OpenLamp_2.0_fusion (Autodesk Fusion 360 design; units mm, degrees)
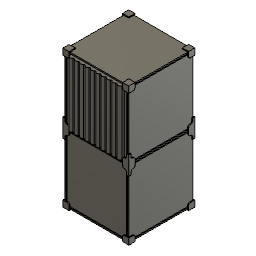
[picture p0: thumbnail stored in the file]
parameter "panel_l" = 100
parameter "proportion_const" = 8.3333 (= "panel_l / 12")
sketch "Sketch1" plane through (0, 0, 0) normal (0, 1, 0) x axis (1, 0, 0)
  line L1 (-50, 50) -> (50, 50)
  line L2 (-50, -50) -> (-50, 50)
  line L3 (50, -50) -> (-50, -50)
  line L4 (50, 50) -> (50, -50)
  line L5 (-50, -50) -> (50, 50)
  line L6 (50, -50) -> (-50, 50)
  point P6 (0, 0)
  point P1 (0, 0)
  point P4 (-50, -50)
  point P5 (50, -50)
  point P3 (-50, 50)
  horizontal L1
  perpendicular L1 L2
  parallel L1 L3
  parallel L2 L4
  coincident L5 P6
  coincident L6 P6
  coincident P1 P6
  dimension "d1" distance P4 P5 = 100 (= "panel_length")
  dimension "panel_length" distance P3 P4 = 100 (= "panel_l")
  dimension "panel_gap" distance = 1.5
  dimension "connector_thickness" distance = 1.5
  dimension "d55" distance = 9
  dimension "d122" distance = 8.3333 (= "proportion_const")
extrude "Extrude1" new body sketch "Sketch1" profile of L1 L2 L3 L4 along normal blind 2 named "panel_thickness"
work_plane "WorkPlane1" AlongDistance 1.5 (= "panel_gap")
sketch "Sketch3" plane through (0, 3.5, 0) normal (0, 1, 0) x axis (-1, 0, 0)
  line L1 (0, -142.7236) -> (0, 0)
  line L2 (48, -50) -> (50, -50)
  line L3 (48, 50) -> (48, -50)
  line L4 (50, 50) -> (48, 50)
  line L5 (50, -50) -> (50, 50)
  line L6 (50, 50) -> (50, -50)
  line L7 (-144.094, 0) -> (0, 0)
  line L8 (50, -50) -> (-50, -50)
  line L9 (-50, 50) -> (50, 50)
  line L10 (-50, -50) -> (-50, 50)
  line L11 (-48, 50) -> (-48, -50)
  line L12 (-50, 50) -> (-48, 50)
  line L13 (-48, -50) -> (-50, -50)
  line L14 (-46.5, 48) -> (46.5, 48)
  line L15 (-46.5, 50) -> (-46.5, 48)
  line L16 (46.5, 50) -> (-46.5, 50)
  line L17 (46.5, 48) -> (46.5, 50)
  line L18 (46.5, -50) -> (-46.5, -50)
  line L19 (-46.5, -48) -> (46.5, -48)
  line L20 (46.5, -48) -> (46.5, -50)
  line L21 (-46.5, -50) -> (-46.5, -48)
  point P1 (0, 0)
  point P2 (0, 0)
  point P10 (0, 0)
  point P4 (50, -50)
  point P15 (-50, -50)
  point P5 (48, -50)
  point P16 (-48, -50)
  point P6 (48, 50)
  point P17 (-48, 50)
  point P7 (50, 50)
  point P14 (-50, 50)
  point P18 (46.5, 48)
  point P24 (46.5, -48)
  point P19 (-46.5, 48)
  point P25 (-46.5, -48)
  point P20 (-46.5, 50)
  point P22 (-46.5, -50)
  point P21 (46.5, 50)
  point P23 (46.5, -50)
  coincident P1 P2
  horizontal L2
  vertical L3
  horizontal L4
  vertical L5
  collinear L5 L6
  coincident P1 P10
  perpendicular L1 L7
  vertical L1
  collinear L2 L8
  collinear L4 L9
  symmetric L1 P4 P15
  symmetric L1 P5 P16
  symmetric L1 P6 P17
  symmetric L1 P7 P14
  horizontal L14
  vertical L15
  horizontal L16
  vertical L17
  collinear L9 L16
  symmetric L7 P18 P24
  symmetric L7 P19 P25
  symmetric L7 P20 P22
  symmetric L7 P21 P23
  dimension "d33" distance L3 L5 = 2 (= "panel_thickness")
  dimension "d34" distance L3 L17 = 1.5 (= "panel_gap")
  dimension "d35" distance L11 L15 = 1.5 (= "d34")
  dimension "d36" distance L14 L16 = 2 (= "panel_thickness")
extrude "Extrude4" new body sketch "Sketch3" profile of L2 L3 L4 L5 L6 L8 L9 L10 L11 L12 L13 L14 L15 L16 L17 L18 L19 L20 L21 along normal blind 100 (= "panel_l")
work_plane "WorkPlane2"
mirror "Mirror1" mirrorStitchTolerance 0.1 bodies "Lamp Holder"
work_plane "WorkPlane3"
mirror "Mirror2" mirrorStitchTolerance 0.1 bodies "Lampshade"
sketch "Sketch1" plane through (0, 0, 50) normal (0, 0, 1) x axis (1, 0, 0)
  line L1 (46.5, 3.5) -> (-46.5, 3.5)
  line L2 (46.5, 103.5) -> (46.5, 3.5)
  line L3 (-46.5, 103.5) -> (46.5, 103.5)
  line L4 (-46.5, 3.5) -> (-46.5, 103.5)
  line L5 (41.6667, 0) -> (50, 0)
  line L6 (41.6667, 8.3333) -> (41.6667, 0)
  line L7 (50, 8.3333) -> (41.6667, 8.3333)
  line L8 (50, 0) -> (50, 8.3333)
  line L9 (50, 8.3333) -> (50, 0)
  line L10 (50, 103.5) -> (50, 3.5)
  line L11 (41.6667, 2.15) -> (50, 2.15)
  line L12 (50, 0) -> (-50, 0)
  line L13 (46.5, 8.3333) -> (46.5, 2.15)
  line L14 (47.8, 2.15) -> (47.8, 8.3333)
  line L15 (41.6667, 3.45) -> (50, 3.45)
  line L16 (51.5, 0) -> (41.6667, 0)
  line L17 (51.5, -1.5) -> (51.5, 0)
  line L18 (41.6667, -1.5) -> (51.5, -1.5)
  line L19 (41.6667, 0) -> (41.6667, -1.5)
  line L20 (50, -0.05) -> (41.6667, -0.05)
  line L21 (50, -1.5) -> (50, 0)
  point P13 (50, 2.15)
  point P14 (41.6667, 2.15)
  point P17 (46.5, 2.15)
  point P18 (46.5, 8.3333)
  point P19 (47.8, 8.3333)
  point P20 (47.8, 2.15)
  point P21 (50, 3.45)
  point P22 (41.6667, 3.45)
  point P26 (41.6667, -0.05)
  point P16 (50, 0)
  point P27 (50, 0)
  point P28 (50, -1.5)
  point P29 (50, -0.05)
  point P7 (41.6667, 0)
  point P8 (41.6667, 8.3333)
  horizontal L5
  vertical L6
  horizontal L7
  collinear L9 L10
  coincident L8 P13
  coincident L6 P14
  perpendicular L6 L11
  collinear L5 L12
  coincident L11 P17
  coincident L7 P18
  perpendicular L7 L13
  coincident L7 P19
  coincident L11 P20
  perpendicular L11 L14
  coincident L9 P21
  coincident L6 P22
  perpendicular L6 L15
  horizontal L16
  vertical L17
  horizontal L18
  vertical L19
  vertical L8
  coincident L19 P26
  perpendicular L17 L20
  coincident P16 P27
  coincident L18 P28
  perpendicular L18 L21
  coincident L21 P29
  dimension "d37" distance L6 L9 = 8.3333 (= "proportion_const")
  dimension "d38" distance P7 P8 = 8.3333 (= "d37")
  dimension "d40" distance L5 L11 = 2.15
  dimension "d42" distance L11 L15 = 1.3 (= "panel_gap - 0.2 mm")
  dimension "d43" distance L13 L14 = 1.3 (= "panel_gap - 0.2 mm")
  dimension "d72" distance L17 L19 = 9.8333 (= "d37 + connector_thickness")
  dimension "d73" distance L5 L18 = 1.5 (= "connector_thickness")
  dimension "d87" distance L9 L14 = 2.2 (= "panel_thickness + 0.2 mm")
  dimension "d88" distance L16 L20 = 0.05
extrude "Extrude1" new body sketch "Sketch1" profile of L1 L2 L5 L6 L7 L8 L9 L10 L11 L12 L13 L14 L15 L16 along normal blind 1.5 (= "connector_thickness")
sketch "Sketch2" plane through (50, 0, 0) normal (1, 0, 0) x axis (0, 0, -1)
  line L1 (50, 3.5) -> (-50, 3.5)
  line L2 (50, 103.5) -> (50, 3.5)
  line L3 (-50, 103.5) -> (50, 103.5)
  line L4 (-50, 3.5) -> (-50, 103.5)
  line L5 (-50, 103.5) -> (-50, 3.5)
  line L6 (-41.6667, 8.3333) -> (-50, 8.3333)
  line L7 (-41.6667, 0) -> (-41.6667, 8.3333)
  line L8 (-50, 0) -> (-41.6667, 0)
  line L9 (-50, 8.3333) -> (-50, 0)
  line L10 (-51.5, 8.3333) -> (-50, 8.3333)
  line L11 (-51.5, 0) -> (-51.5, 8.3333)
  line L12 (-50, 0) -> (-51.5, 0)
  line L13 (-50, 8.3333) -> (-50, 0)
  line L14 (50, 0) -> (-50, 0)
  point P8 (-50, 8.3333)
  point P9 (-41.6667, 8.3333)
  point P10 (-41.6667, 0)
  point P11 (-50, 0)
  horizontal L6
  vertical L7
  horizontal L8
  vertical L9
  coincident L4 P8
  horizontal L10
  vertical L11
  horizontal L12
  vertical L13
  collinear L8 L14
  dimension "d46" distance P9 P10 = 8.3333 (= "proportion_const")
  dimension "d47" distance P10 P11 = 8.3333 (= "d46")
  dimension "d48" distance L11 L13 = 1.5 (= "connector_thickness")
  dimension "d49" distance L10 L12 = 8.3333 (= "d46")
extrude "Extrude2" add sketch "Sketch2" profile of L1 L4 L5 L6 L7 L8 L9 L10 L11 L12 L13 L14 along normal blind 1.5 (= "connector_thickness")
extrude "Extrude3" add sketch "Sketch1" profile of L6 L7 L8 L9 L11 L13 L14 L15 to an object
sketch "Sketch3" plane through (0, 3.45, 0) normal (0, 1, 0) x axis (-1, 0, 0)
  line L1 (-46.5, 50) -> (-41.6667, 50)
  line L2 (-46.5, 41.6667) -> (-46.5, 50)
  line L3 (-41.6667, 41.6667) -> (-46.5, 41.6667)
  line L4 (-41.6667, 50) -> (-41.6667, 41.6667)
  line L5 (-50, 50) -> (-41.6667, 50)
  line L6 (-38.6667, 48.5038) -> (-41.6667, 47.7)
  line L7 (-38.1667, 46.6378) -> (-38.6667, 48.5038)
  line L8 (-35.4, 47.7) -> (-41.6667, 47.7)
  line L9 (-38.1667, 46.6378) -> (-41.6667, 45.7)
  line L10 (-41.6667, 47.7) -> (-46.5, 47.7)
  line L11 (-41.6667, 45.7) -> (-46.5, 45.7)
  line L12 (-41.6667, 45.7) -> (-41.6667, 47.7)
  point P11 (-46.5, 47.7)
  point P12 (-41.6667, 47.7)
  point P13 (-46.5, 45.7)
  point P14 (-41.6667, 45.7)
  point P9 (-38.1667, 46.6378)
  perpendicular L4 L8
  perpendicular L7 L9
  parallel L6 L9
  coincident L2 P11
  coincident L4 P12
  perpendicular L4 L10
  coincident L2 P13
  coincident L4 P14
  perpendicular L4 L11
  coincident L4 P14
  dimension "d60" angle L6 L8 = 15
  dimension "d211" distance L5 L10 = 2.3
  dimension "d212" distance L10 L11 = 2
  dimension "d214" distance P9 P14 = 3.5
extrude "Extrude4" add sketch "Sketch3" profile of L2 L4 L10 L11 L12 to an object
extrude "Extrude5" sketch "Sketch3" profile of L4 L6 L7 L9 L12 to an object
extrude "Extrude6" add sketch "Sketch1" profile of L5 L12 L16 L17 L18 L19 along normal blind 1.5 (= "connector_thickness")
extrude "Extrude7" add sketch "Sketch1" profile of L16 L17 L18 L19 L20 L21 to an object
fillet "Fillet2" radius 3 (= "connector_thickness * 2")
sketch "Sketch7" plane through (41.6667, 0, 0) normal (-1, 0, 0) x axis (0, 0, 1)
  line L1 (50, 5.3333) -> (51.5, 5.3333)
  line L2 (50, 3.45) -> (50, 5.3333)
  line L3 (47.7, 3.45) -> (50, 3.45)
  line L4 (41.6667, 2.15) -> (41.6667, 3.45)
  line L5 (50, 2.15) -> (41.6667, 2.15)
  line L6 (50, -0.05) -> (50, 2.15)
  line L7 (41.6667, -0.05) -> (50, -0.05)
  line L8 (41.6667, -1.5) -> (41.6667, -0.05)
  line L9 (51.5, -1.5) -> (41.6667, -1.5)
  line L10 (51.5, 5.3333) -> (51.5, -1.5)
  line L11 (44.7, 2.15) -> (44.7, 3.45)
  line L12 (45.7, 3.45) -> (47.7, 3.45)
  line L13 (41.6667, 3.45) -> (45.7, 3.45)
  point P14 (44.7, 2.15)
  perpendicular L5 L11
  coincident L5 P14
extrude "Extrude9" cut sketch "Sketch7" profile of L4 L5 L11 against normal blind 3.375
extrude "Extrude11" add of existing geometry blind 0.7
sketch "Sketch8" plane through (0, 0, 44.7) normal (0, 0, -1) x axis (-1, 0, 0)
  line L1 (-41.6667, 4.15) -> (-41.6667, 2.15)
  line L2 (-45.0417, 2.15) -> (-45.0417, 4.15)
  line L3 (-41.6667, 2.15) -> (-45.0417, 2.15)
  line L4 (-41.6667, 1.494) -> (-45.0417, 2.15)
  line L5 (-41.6667, 2.15) -> (-50, 2.15)
  line L6 (-41.6667, 2.144) -> (-41.6667, 1.494)
  line L7 (-45.0417, 4.15) -> (-41.6667, 4.15)
  line L8 (-41.6667, 3.494) -> (-45.0417, 4.15)
  line L9 (-41.6667, 1.494) -> (-41.6667, 3.494)
  point P5 (-45.0417, 2.15)
  point P6 (-45.0417, 2.15)
  point P10 (-41.6667, 2.144)
  point P11 (-41.6667, 3.494)
  point P4 (-45.0417, 4.15)
  point P12 (-45.0417, 4.15)
  coincident P5 P6
  coincident L1 P10
  perpendicular L3 L6
  coincident L1 P11
  parallel L4 L8
  coincident P4 P12
  dimension "d110" angle L4 L5 = 11
extrude "Extrude10" add sketch "Sketch8" profile of L2 L3 L4 L5 to an object from offset 0.5
sketch "Sketch13" plane through (46.5, 0, 0) normal (-1, 0, 0) x axis (0, 0, 1)
  line L1 (45.7, 4.15) -> (41.6667, 4.15)
  line L2 (45.7, 8.3333) -> (45.7, 4.15)
  line L3 (41.6667, 8.3333) -> (45.7, 8.3333)
  line L4 (41.6667, 4.15) -> (41.6667, 8.3333)
  line L5 (43.6833, 8.3333) -> (41.6667, 6.2417)
  point P6 (41.6667, 6.2417)
  point P7 (43.6833, 8.3333)
  midpoint L4 P6
  midpoint L3 P7
extrude "Extrude19" cut sketch "Sketch13" profile of L3 L4 L5 against normal blind 1.3
mirror "Mirror1" mirrorStitchTolerance 0.1
mirror "Mirror2" mirrorStitchTolerance 0.1
mirror "Mirror3" mirrorStitchTolerance 0.1
sketch "Sketch1" plane through (0, 0, 50) normal (0, 0, 1) x axis (1, 0, 0)
  line L1 (-48, 3.5) -> (-50, 3.5)
  line L2 (-48, 103.5) -> (-48, 3.5)
  line L3 (-50, 103.5) -> (-48, 103.5)
  line L4 (-50, 3.5) -> (-50, 103.5)
sketch "Sketch1" plane through (0, 0, 50) normal (0, 0, 1) x axis (1, 0, 0)
  line L1 (-46.5, 208.5) -> (46.5, 208.5)
  line L2 (-46.5, 108.5) -> (-46.5, 208.5)
  line L3 (46.5, 108.5) -> (-46.5, 108.5)
  line L4 (46.5, 208.5) -> (46.5, 108.5)
  line L5 (50, 103.5) -> (50, 3.5)
  line L6 (50, 108.5) -> (50, 208.5)
  line L7 (41.6667, 113.3333) -> (50, 113.3333)
  line L8 (41.6667, 98.6667) -> (41.6667, 113.3333)
  line L9 (50, 98.6667) -> (41.6667, 98.6667)
  line L10 (50, 113.3333) -> (50, 98.6667)
  line L11 (-46.5, 103.5) -> (46.5, 103.5)
  line L12 (50, 107) -> (-50, 107)
  line L13 (50, 105) -> (-50, 105)
  line L14 (48, 120.6667) -> (48, 113.3333)
  line L15 (50, 120.6667) -> (48, 120.6667)
  line L16 (46.5, 103.5) -> (46.5, 3.5)
  line L17 (50, 106) -> (41.6667, 106)
  line L18 (48, 91.3333) -> (48, 98.6667)
  line L19 (50, 91.3333) -> (48, 91.3333)
  line L20 (50, 107.1) -> (41.6667, 107.1)
  line L21 (50, 108.4) -> (41.6667, 108.4)
  line L22 (50, 103.6) -> (41.6667, 103.6)
  line L23 (50, 104.9) -> (41.6667, 104.9)
  line L24 (46.5, 113.3333) -> (46.5, 108.4)
  line L25 (47.8, 108.4) -> (47.8, 113.3333)
  line L26 (46.5, 98.6667) -> (46.5, 103.6)
  line L27 (47.8, 103.6) -> (47.8, 98.6667)
  point P10 (50, 113.3333)
  point P20 (48, 113.3333)
  point P22 (50, 120.6667)
  point P24 (41.6667, 106)
  point P25 (50, 106)
  point P26 (48, 98.6667)
  point P21 (48, 120.6667)
  point P27 (48, 91.3333)
  point P28 (50, 91.3333)
  point P29 (41.6667, 107.1)
  point P30 (50, 107.1)
  point P31 (41.6667, 108.4)
  point P32 (50, 108.4)
  point P35 (41.6667, 104.9)
  point P36 (50, 104.9)
  point P33 (41.6667, 103.6)
  point P34 (50, 103.6)
  point P37 (46.5, 108.4)
  point P38 (46.5, 113.3333)
  point P39 (47.8, 113.3333)
  point P40 (47.8, 108.4)
  point P41 (46.5, 103.6)
  point P42 (46.5, 98.6667)
  point P43 (47.8, 98.6667)
  point P44 (47.8, 103.6)
  point P9 (50, 108.5)
  horizontal L7
  vertical L8
  horizontal L9
  vertical L10
  coincident L6 P10
  coincident L7 P20
  perpendicular L7 L14
  coincident L6 P22
  perpendicular L6 L15
  midpoint L8 P24
  midpoint L10 P25
  symmetric P20 L17 P26
  symmetric P21 L17 P27
  symmetric P22 L17 P28
  coincident L8 P29
  coincident L10 P30
  perpendicular L10 L20
  coincident L8 P31
  coincident L10 P32
  perpendicular L10 L21
  symmetric L17 P29 P35
  symmetric L17 P30 P36
  symmetric L17 P31 P33
  symmetric L17 P32 P34
  coincident L21 P37
  coincident L7 P38
  coincident L4 P38
  perpendicular L7 L24
  coincident L7 P39
  coincident L21 P40
  perpendicular L21 L25
  symmetric L17 P37 P41
  symmetric L17 P38 P42
  symmetric L17 P39 P43
  symmetric L17 P40 P44
  dimension "d139" distance L7 L13 = 8.3333 (= "proportion_const")
  dimension "d140" distance L9 L12 = 8.3333 (= "d139")
  dimension "d141" distance L8 L10 = 8.3333 (= "d139")
  dimension "d142" distance L7 L15 = 7.3333 (= "d139 - 1 mm")
  dimension "d147" distance P21 P22 = 2 (= "panel_thickness")
  dimension "d151" distance L12 L20 = 0.1
  dimension "d152" distance P9 L21 = 0.1
  dimension "d153" distance L24 L25 = 1.3 (= "panel_gap - 0.2 mm")
extrude "Extrude1" new body sketch "Sketch1" profile of L3 L4 L5 L6 L7 L8 L9 L10 L11 L12 L13 L14 L15 L16 L18 L19 L20 L21 L22 L23 L24 L25 L26 L27 along normal blind 1.5 (= "connector_thickness")
sketch "Sketch2" plane through (50, 0, 0) normal (1, 0, 0) x axis (0, 0, -1)
  line L1 (-50, 208.5) -> (50, 208.5)
  line L2 (-50, 108.5) -> (-50, 208.5)
  line L3 (50, 108.5) -> (-50, 108.5)
  line L4 (50, 208.5) -> (50, 108.5)
  line L5 (-50, 120.6667) -> (-50, 91.3333)
  line L6 (-51.5, 120.6667) -> (-50, 120.6667)
  line L7 (-41.6667, 113.3333) -> (-50, 113.3333)
  line L8 (-41.6667, 98.6667) -> (-41.6667, 113.3333)
  line L9 (-50, 98.6667) -> (-41.6667, 98.6667)
  line L10 (-50, 113.3333) -> (-50, 98.6667)
  line L11 (50, 105) -> (-50, 105)
  line L12 (50, 107) -> (-50, 107)
  line L13 (-48, 120.6667) -> (-48, 113.3333)
  line L14 (-50, 120.6667) -> (-48, 120.6667)
  line L15 (-50, 106) -> (-41.6667, 106)
  line L16 (-50, 91.3333) -> (-48, 91.3333)
  line L17 (-48, 91.3333) -> (-48, 98.6667)
  point P6 (-50, 120.6667)
  point P9 (-50, 113.3333)
  point P17 (-48, 113.3333)
  point P7 (-50, 120.6667)
  point P19 (-50, 120.6667)
  point P20 (-41.6667, 106)
  point P21 (-50, 106)
  point P24 (-48, 98.6667)
  point P18 (-48, 120.6667)
  point P22 (-48, 91.3333)
  point P23 (-50, 91.3333)
  vertical L5
  coincident L2 P6
  horizontal L7
  vertical L8
  horizontal L9
  vertical L10
  coincident L2 P9
  coincident L7 P17
  perpendicular L7 L13
  coincident P7 P19
  midpoint L8 P20
  midpoint L5 P21
  symmetric P17 L15 P24
  symmetric P18 L15 P22
  symmetric P19 L15 P23
  horizontal L14
  dimension "d143" distance L7 L11 = 8.3333 (= "proportion_const")
  dimension "d144" distance L9 L12 = 8.3333 (= "d143")
  dimension "d145" distance L5 L8 = 8.3333 (= "proportion_const")
  dimension "d148" distance P18 P19 = 2
extrude "Extrude2" add sketch "Sketch2" profile of L2 L3 L5 L7 L8 L9 L10 L11 L12 L13 L14 L16 L17 along normal blind 1.5 (= "connector_thickness")
extrude "Extrude3" add sketch "Sketch1" profile of L4 L7 L8 L9 L10 L16 L20 L21 L22 L23 L24 L25 L26 L27 against normal blind 8.3333
sketch "Sketch3" plane through (0, 108.4, 0) normal (0, 1, 0) x axis (-1, 0, 0)
  line L1 (-46.5, 50) -> (-41.6667, 50)
  line L2 (-46.5, 41.6667) -> (-46.5, 50)
  line L3 (-41.6667, 41.6667) -> (-46.5, 41.6667)
  line L4 (-41.6667, 50) -> (-41.6667, 41.6667)
  line L5 (-41.6667, 47.7) -> (-46.5, 47.7)
  line L6 (-41.6667, 45.7) -> (-41.6667, 47.7)
  line L7 (-46.5, 45.7) -> (-41.6667, 45.7)
  line L8 (-46.5, 47.7) -> (-46.5, 45.7)
  line L9 (-38.1667, 48.6378) -> (-41.6667, 47.7)
  line L10 (-35.9947, 47.7) -> (-41.6667, 47.7)
  line L11 (-38.1667, 46.6378) -> (-41.6667, 45.7)
  line L12 (-38.1667, 48.6378) -> (-38.1667, 46.6378)
  point P6 (-46.5, 47.7)
  horizontal L5
  vertical L6
  horizontal L7
  vertical L8
  coincident L2 P6
  horizontal L10
  parallel L9 L11
  vertical L12
  collinear L4 L6
  dimension "d156" distance L5 L7 = 2
  dimension "d158" distance L1 L5 = 2.3
  dimension "d161" angle L9 L10 = 15
  dimension "d220" distance L6 L12 = 3.5
extrude "Extrude4" add sketch "Sketch3" profile of L2 L4 L5 L6 L7 L8 L9 L11 along normal blind 4.9333
extrude "Extrude5" add sketch "Sketch3" profile of L4 L6 L9 L11 L12 along normal blind 4.9333
mirror "Mirror1" mirrorStitchTolerance 0.1
sketch "Sketch7" plane through (41.6667, 0, 0) normal (-1, 0, 0) x axis (0, 0, 1)
  line L1 (50, 108.4) -> (50, 113.3333)
  line L2 (47.7, 108.4) -> (50, 108.4)
  line L3 (41.6667, 107.1) -> (41.6667, 108.4)
  line L4 (50, 107.1) -> (41.6667, 107.1)
  line L5 (50, 104.9) -> (50, 107.1)
  line L6 (41.6667, 104.9) -> (50, 104.9)
  line L7 (41.6667, 103.6) -> (41.6667, 104.9)
  line L8 (45.7, 103.6) -> (41.6667, 103.6)
  line L9 (50, 103.6) -> (47.7, 103.6)
  line L10 (50, 98.6667) -> (50, 103.6)
  line L11 (51.5, 98.6667) -> (50, 98.6667)
  line L12 (51.5, 113.3333) -> (51.5, 98.6667)
  line L13 (50, 113.3333) -> (51.5, 113.3333)
  line L14 (44.7, 104.9) -> (44.7, 103.6)
  line L15 (47.7, 103.6) -> (45.7, 103.6)
  line L16 (45.7, 108.4) -> (47.7, 108.4)
  line L17 (41.6667, 108.4) -> (45.7, 108.4)
  point P17 (44.7, 103.6)
  point P18 (44.7, 104.9)
  point P11 (45.7, 103.6)
  coincident L8 P17
  coincident L6 P18
  perpendicular L6 L14
  dimension "d225" distance P11 L14 = 1
extrude "Extrude10" cut sketch "Sketch7" profile of L6 L7 L8 L14 against normal blind 3.375
extrude "Extrude11" add of existing geometry blind 0.7
extrude "Extrude13" add of existing geometry blind 0.7
sketch "Sketch8" plane through (0, 0, 41.6667) normal (0, 0, -1) x axis (-1, 0, 0)
  line L1 (-45.0417, 104.9) -> (-45.0417, 102.9)
  line L2 (-50, 104.9) -> (-45.0417, 104.9)
  line L3 (-50, 107.1) -> (-50, 104.9)
  line L4 (-41.6667, 107.1) -> (-50, 107.1)
  line L5 (-41.6667, 109.1) -> (-41.6667, 107.1)
  line L6 (-46.5, 113.3333) -> (-46.5, 109.1)
  line L7 (-47.8, 113.3333) -> (-46.5, 113.3333)
  line L8 (-47.8, 108.4) -> (-47.8, 113.3333)
  line L9 (-50, 108.4) -> (-47.8, 108.4)
  line L10 (-51.5, 113.3333) -> (-50, 113.3333)
  line L11 (-51.5, 98.6667) -> (-51.5, 113.3333)
  line L12 (-50, 98.6667) -> (-51.5, 98.6667)
  line L13 (-47.8, 103.6) -> (-50, 103.6)
  line L14 (-47.8, 98.6667) -> (-47.8, 103.6)
  line L15 (-46.5, 98.6667) -> (-47.8, 98.6667)
  line L16 (-46.5, 102.9) -> (-46.5, 98.6667)
  line L17 (-41.6667, 105.556) -> (-45.0417, 104.9)
  line L18 (-41.6667, 103.556) -> (-41.6667, 105.556)
  line L19 (-45.0417, 102.9) -> (-41.6667, 103.556)
  line L20 (-41.6667, 102.9) -> (-41.6667, 104.9)
  line L21 (-43.1667, 104.9) -> (-45.0417, 104.9)
  line L22 (-45.0417, 102.9) -> (-46.5, 102.9)
  line L23 (-46.5, 109.1) -> (-41.6667, 109.1)
  line L24 (-50, 113.3333) -> (-50, 108.4)
  line L25 (-50, 103.6) -> (-50, 98.6667)
  point P3 (-45.0417, 104.9)
  point P22 (-45.0417, 104.9)
  point P2 (-45.0417, 102.9)
  point P30 (-45.0417, 102.9)
  coincident P3 P22
  perpendicular L2 L18
  parallel L17 L19
  collinear L18 L20
  perpendicular L1 L21
  coincident P2 P30
  dimension "d189" angle L17 L21 = 11
extrude "Extrude12" add sketch "Sketch8" profile of L1 L17 L18 L19 L20 against normal blind 2.5
fillet "Fillet7" radius 3 (= "connector_thickness * 2") 3.3 (= "connector_thickness * 2.2")
sketch "Sketch11" plane through (46.5, 0, 0) normal (-1, 0, 0) x axis (0, 0, 1)
  line L1 (45.7, 109.1) -> (41.6667, 109.1)
  line L2 (45.7, 113.6974) -> (45.7, 109.1)
  line L3 (45.7, 113.6974) -> (41.6667, 113.6974)
  line L4 (41.6667, 109.1) -> (41.6667, 113.6974)
  line L5 (50, 113.6974) -> (41.6667, 113.6974)
  line L6 (45.7, 98.3026) -> (41.6667, 98.3026)
  line L7 (50, 98.3026) -> (41.6667, 98.3026)
  line L8 (41.6667, 117.6974) -> (41.6667, 113.6974)
  line L9 (50, 117.6974) -> (41.6667, 117.6974)
  line L10 (50, 113.6974) -> (50, 117.6974)
  line L11 (41.6667, 94.3026) -> (41.6667, 98.3026)
  line L12 (50, 94.3026) -> (41.6667, 94.3026)
  line L13 (50, 98.3026) -> (50, 94.3026)
  point P5 (41.6667, 113.6974)
  point P6 (41.6667, 113.6974)
  point P9 (41.6667, 98.3026)
  point P12 (41.6667, 98.3026)
  point P11 (50, 98.3026)
  point P13 (50, 98.3026)
  point P8 (50, 113.6974)
  point P16 (50, 113.6974)
  point P17 (41.6667, 98.3026)
  point P20 (50, 98.3026)
  coincident P5 P6
  perpendicular L4 L5
  coincident P9 P12
  coincident P11 P13
  perpendicular L3 L8
  coincident P8 P16
  horizontal L9
  vertical L10
  coincident P9 P17
  perpendicular L6 L11
  perpendicular L11 L12
  coincident P11 P20
  vertical L13
  dimension "d388" distance L5 L9 = 4
  dimension "d389" distance L7 L12 = 4 (= "d388")
extrude "Extrude17" cut sketch "Sketch11" profile of L3 L5 L6 L7 L8 L9 L10 L11 L12 L13 against normal blind 2
sketch "Sketch12" plane through (46.5, 0, 0) normal (-1, 0, 0) x axis (0, 0, 1)
  line L1 (45.7, 109.1) -> (41.6667, 109.1)
  line L2 (45.7, 113.6974) -> (45.7, 109.1)
  line L3 (45.7, 113.6974) -> (41.6667, 113.6974)
  line L4 (41.6667, 109.1) -> (41.6667, 113.6974)
  line L5 (43.6833, 113.6974) -> (41.6667, 111.3987)
  line L6 (41.6667, 102.9) -> (45.7, 102.9)
  line L7 (41.6667, 98.3026) -> (41.6667, 102.9)
  line L8 (41.6667, 98.3026) -> (45.7, 98.3026)
  line L9 (45.7, 102.9) -> (45.7, 98.3026)
  line L10 (43.6833, 98.3026) -> (41.6667, 100.6013)
  point P7 (43.6833, 113.6974)
  point P6 (41.6667, 111.3987)
  point P13 (43.6833, 98.3026)
  point P12 (41.6667, 100.6013)
  midpoint L3 P7
  midpoint L4 P6
  midpoint L8 P13
  coincident L7 P12
  midpoint L7 P12
extrude "Extrude18" cut sketch "Sketch12" profile of L3 L4 L5 against normal blind 1.3
extrude "Extrude19" cut sketch "Sketch12" profile of L7 L8 L10 against normal blind 1.3
mirror "Mirror2" mirrorStitchTolerance 0.1
mirror "Mirror3" mirrorStitchTolerance 0.1
sketch "Sketch10" plane through (0, 109.1, 0) normal (0, 1, 0) x axis (-1, 0, 0)
  line L1 (41.6667, 45.9) -> (46.5, 45.9)
  line L2 (41.6667, 41.6667) -> (41.6667, 45.9)
  line L3 (46.5, 41.6667) -> (41.6667, 41.6667)
  line L4 (46.5, 45.9) -> (46.5, 41.6667)
  line L5 (41.6667, 41.6667) -> (46.5, 45.9)
  circle C1 centre (44.0833, 43.7833) radius 1.5
  circle C2 centre (-44.0833, -43.7833) radius 1.5
  point P2 (46.5, 45.9)
  point P6 (46.5, 45.9)
  point P4 (41.6667, 41.6667)
  point P7 (41.6667, 41.6667)
  point P8 (44.0833, 43.7833)
  coincident P2 P6
  coincident P4 P7
  midpoint L5 P8
  dimension "d261" diameter C1 = 3
  dimension "d280" C-Pattern1-Angle = 360
extrude "Extrude15" cut sketch "Sketch10" profile of C1 C2 against normal blind 0.2
sketch "Sketch4" plane through (0, 107, 0) normal (0, 1, 0) x axis (-1, 0, 0)
  line L1 (-50, -50) -> (-50, 50)
  line L2 (50, -50) -> (-50, -50)
  line L3 (50, 50) -> (50, -50)
  line L4 (-50, 50) -> (50, 50)
  line L5 (-9.1, 9.1) -> (9.1, 9.1)
  line L6 (-9.1, -9.1) -> (-9.1, 9.1)
  line L7 (9.1, -9.1) -> (-9.1, -9.1)
  line L8 (9.1, 9.1) -> (9.1, -9.1)
  line L9 (-9.1, -9.1) -> (9.1, 9.1)
  line L10 (9.1, -9.1) -> (-9.1, 9.1)
  line L11 (0, 9.1) -> (0, 0)
  line L12 (12.1, -12.1) -> (-12.1, -12.1)
  line L13 (12.1, 12.1) -> (12.1, -12.1)
  line L14 (-12.1, 12.1) -> (12.1, 12.1)
  line L15 (-12.1, -12.1) -> (-12.1, 12.1)
  circle C1 centre (0, 0) radius 9.1
  point P1 (0, 0)
  point P6 (0, 0)
  point P7 (0, 0)
  point P12 (0, 0)
  point P13 (0, 0)
  point P14 (0, 9.1)
  point P15 (0, 9.1)
  coincident P1 P6
  coincident P1 P7
  horizontal L5
  perpendicular L5 L6
  parallel L5 L7
  parallel L6 L8
  coincident L9 P12
  coincident L10 P12
  coincident P6 P12
  coincident P6 P13
  coincident C1 P14
  perpendicular L5 L11
  midpoint L5 P15
  coincident P14 P15
  equal L5 L8
  dimension "d262" diameter C1 = 18.2
  dimension "d327" = 3
extrude "Extrude8" cut sketch "Sketch4" profile of C1 L5 L6 L7 L8 L15 L14 L13 L12 against normal blind 5
component_from_bodies "Body->Comp"
offset_faces "OffsetFaces1" distance -0.2
sketch "Sketch1" plane through (0, 208.5, 0) normal (0, 1, 0) x axis (-1, 0, 0)
  line L1 (-46.5, 49.8) -> (46.5, 49.8)
  line L2 (-46.5, 48) -> (-46.5, 49.8)
  line L3 (46.5, 48) -> (-46.5, 48)
  line L4 (46.5, 49.8) -> (46.5, 48)
  line L5 (37.5883, 54.081) -> (37.5124, 49.8)
  arc A1 centre (37.5883, 50.581) radius 3.5 clockwise from (34.1765, 49.8) to (41, 49.8)
  arc A2 centre (29.2549, 50.581) radius 3.5 clockwise from (25.8432, 49.8) to (32.6667, 49.8)
  arc A3 centre (20.9216, 50.581) radius 3.5 clockwise from (17.5099, 49.8) to (24.3333, 49.8)
  arc A4 centre (12.5883, 50.581) radius 3.5 clockwise from (9.1765, 49.8) to (16, 49.8)
  arc A5 centre (4.2549, 50.581) radius 3.5 clockwise from (0.8432, 49.8) to (7.6667, 49.8)
  arc A6 centre (-4.0784, 50.581) radius 3.5 clockwise from (-7.4901, 49.8) to (-0.6667, 49.8)
  arc A7 centre (-12.4117, 50.581) radius 3.5 clockwise from (-15.8235, 49.8) to (-9, 49.8)
  arc A8 centre (-20.7451, 50.581) radius 3.5 clockwise from (-24.1568, 49.8) to (-17.3333, 49.8)
  arc A9 centre (-29.0784, 50.581) radius 3.5 clockwise from (-32.4901, 49.8) to (-25.6667, 49.8)
  arc A10 centre (-37.4117, 50.581) radius 3.5 clockwise from (-40.8235, 49.8) to (-34, 49.8)
  point P7 (34.1765, 49.8)
  point P6 (41, 49.8)
  point P36 (37.5124, 49.8)
  point P37 (37.5883, 54.081)
  point P2 (46.5, 49.8)
  coincident L1 P7
  coincident L1 P6
  coincident L1 P36
  midpoint A1 P37
  dimension "d265" radius A1 = 3.5
  dimension "d266" distance P2 P6 = 5.5
  dimension "d397" distance P36 P37 = 4.281 (= "2.9810393521 mm + 0.8 mm + 0.5 mm")
  dimension "d269" R-Pattern1-uDistance = -75
  dimension "d270" R-Pattern1-vDistance = 0
extrude "Extrude1" add sketch "Sketch1" profile of L1 A1 A2 A3 A4 A5 A6 A7 A8 A9 A10 against normal blind 100
fillet "Fillet1" radius 1.5
fillet "Fillet2" radius 2
sketch "Sketch1" plane through (0, 107, 0) normal (0, 1, 0) x axis (-1, 0, 0)
  line L1 (-50, -50) -> (-50, 50)
  line L2 (50, -50) -> (-50, -50)
  line L3 (50, 50) -> (50, -50)
  line L4 (-50, 50) -> (50, 50)
  line L5 (-12.1, -12.1) -> (12.1, -12.1)
  line L6 (-12.1, 12.1) -> (-12.1, -12.1)
  line L7 (12.1, 12.1) -> (-12.1, 12.1)
  line L8 (12.1, -12.1) -> (12.1, 12.1)
  circle C1 centre (0, 0) radius 9
  point P1 (0, 0)
  point P6 (0, 0)
  coincident P1 P6
  dimension "d311" diameter C1 = 18
extrude "Extrude1" new body sketch "Sketch1" profile of C1 along normal blind 8.56
sketch "Sketch2" plane through (0, 115.56, 0) normal (0, 1, 0) x axis (-1, 0, 0)
  line L1 (7.2739, 5.3) -> (-7.2739, 5.3)
  line L2 (7.2739, -5.3) -> (-7.2739, -5.3)
  line L3 (-9, 0) -> (0, 0)
  line L4 (0, -5.3) -> (0, 0)
  circle C1 centre (0, 0) radius 9
  circle C2 centre (-3.3, 5.3) radius 1.65
  circle C3 centre (3.3, -5.3) radius 1.65
  point P3 (-7.2739, 5.3)
  point P4 (7.2739, 5.3)
  point P5 (-7.2739, -5.3)
  point P6 (7.2739, -5.3)
  point P7 (-3.3, 5.3)
  point P1 (0, 0)
  point P8 (0, 0)
  point P9 (-9, 0)
  point P10 (0, 0)
  point P11 (0, -5.3)
  coincident C1 P3
  coincident C1 P4
  horizontal L1
  coincident C1 P5
  coincident C1 P6
  horizontal L2
  coincident L1 P7
  coincident P1 P8
  coincident C1 P9
  horizontal L3
  coincident P1 P10
  midpoint L2 P11
  dimension "d314" distance L1 L2 = 10.6
  dimension "d315" distance P1 L1 = 5.3 (= "d314 / 2")
  dimension "d318" diameter C2 = 3.3
  dimension "d319" distance P7 P9 = 5.7
  dimension "d321" C-Pattern1-Angle = 360
extrude "Extrude2" add sketch "Sketch2" profile of C1 L1 L2 along normal blind 17.04 (= "25.6 mm - 8.56 mm")
extrude "Extrude3" cut sketch "Sketch2" profile of L1 L2 C2 C3 distance 17.04
sketch "Sketch3" plane through (0, 132.6, 0) normal (0, 1, 0) x axis (-1, 0, 0)
  line L1 (7.2739, -5.3) -> (4.95, -5.3)
  line L2 (-1.65, 5.3) -> (7.2739, 5.3)
  line L3 (-7.2739, 5.3) -> (-4.95, 5.3)
  line L4 (1.65, -5.3) -> (-7.2739, -5.3)
  arc A1 centre (3.3, -5.3) radius 1.65 clockwise from (1.65, -5.3) to (4.95, -5.3)
  arc A2 centre (0, 0) radius 9 clockwise from (7.2739, 5.3) to (7.2739, -5.3)
  arc A3 centre (-3.3, 5.3) radius 1.65 clockwise from (-1.65, 5.3) to (-4.95, 5.3)
  arc A4 centre (0, 0) radius 9 clockwise from (-7.2739, -5.3) to (-7.2739, 5.3)
  circle C1 centre (0, 0) radius 7.65
  point P1 (0, 0)
  point P13 (0, 0)
  coincident P1 P13
  dimension "d324" diameter C1 = 15.3
extrude "Extrude4" new body sketch "Sketch3" profile of A1 L1 L2 A3 L3 L4 C1 along normal blind 33
sketch "Sketch1" plane through (0, 107, 0) normal (0, 1, 0) x axis (-1, 0, 0)
  line L1 (-50, -50) -> (-50, 50)
  line L2 (50, -50) -> (-50, -50)
  line L3 (50, 50) -> (50, -50)
  line L4 (-50, 50) -> (50, 50)
  line L5 (7.8842, 5.3) -> (-7.8842, 5.3)
  line L6 (7.8842, -5.3) -> (-7.8842, -5.3)
  line L7 (-12.1, -12.1) -> (12.1, -12.1)
  line L8 (-12.1, 12.1) -> (-12.1, -12.1)
  line L9 (12.1, 12.1) -> (-12.1, 12.1)
  line L10 (12.1, -12.1) -> (12.1, 12.1)
  line L11 (14.1, 14.1) -> (-14.1, 14.1)
  line L12 (14.1, -14.1) -> (14.1, 14.1)
  line L13 (-14.1, -14.1) -> (14.1, -14.1)
  line L14 (-14.1, 14.1) -> (-14.1, -14.1)
  circle C1 centre (0, 0) radius 9.5
  point P1 (0, 0)
  point P6 (0, 0)
  point P7 (-7.8842, 5.3)
  point P8 (7.8842, 5.3)
  point P9 (-7.8842, -5.3)
  point P10 (7.8842, -5.3)
  coincident P1 P6
  coincident C1 P7
  coincident C1 P8
  coincident C1 P9
  coincident C1 P10
  horizontal L5
  dimension "d306" diameter C1 = 19
  dimension "d307" distance L5 L6 = 10.6
  dimension "d308" distance P1 L5 = 5.3 (= "d307 / 2")
  dimension "d339" = -2
extrude "Extrude1" new body sketch "Sketch1" profile of C1 L7 L8 L9 L10 L13 L12 L14 L11 along normal blind 2
extrude "Extrude15" cut of existing geometry blind -10
sketch "Sketch11" plane through (-46.5, 0, 0) normal (1, 0, 0) x axis (0, 0, -1)
  line L1 (-45.7, 207.85) -> (-41.6667, 207.85)
  line L2 (-45.7, 203.6667) -> (-45.7, 207.85)
  line L3 (-41.6667, 205.7583) -> (-45.7, 207.85)
  line L4 (-41.6667, 205.7583) -> (-43.6833, 203.6667)
  line L5 (-41.6667, 207.85) -> (-41.6667, 205.7583)
  line L6 (-43.6833, 203.6667) -> (-45.7, 203.6667)
  circle C1 centre (-43.6833, 206.8042) radius 1
  point P3 (-45.7, 207.85)
  point P6 (-45.7, 207.85)
  point P5 (-41.6667, 205.7583)
  point P7 (-41.6667, 205.7583)
  point P8 (-43.6833, 206.8042)
  coincident P3 P6
  coincident P5 P7
  midpoint L3 P8
  dimension "d290" diameter C1 = 2
extrude "Extrude16" cut sketch "Sketch11" profile of C1 against normal blind 0.2
sketch "Sketch12" plane through (46.5, 0, 0) normal (-1, 0, 0) x axis (0, 0, 1)
  line L1 (-45.7, 207.85) -> (-41.6667, 207.85)
  line L2 (-45.7, 203.6667) -> (-45.7, 207.85)
  line L3 (-42.675, 204.7125) -> (-45.7, 207.85)
  line L4 (-41.6667, 205.7583) -> (-43.6833, 203.6667)
  line L5 (-41.6667, 207.85) -> (-41.6667, 205.7583)
  line L6 (-43.6833, 203.6667) -> (-45.7, 203.6667)
  circle C1 centre (-44.1875, 206.2812) radius 1
  point P3 (-45.7, 207.85)
  point P6 (-45.7, 207.85)
  point P8 (-44.1875, 206.2812)
  point P7 (-42.675, 204.7125)
  coincident P3 P6
  midpoint L3 P8
  midpoint P7 L4
  dimension "d293" diameter C1 = 2
extrude "Extrude17" cut sketch "Sketch12" profile of C1 against normal blind 0.2
delete_face "DeleteFace3"
delete_face "DeleteFace4"
delete_face "DeleteFace5"
extrude "Extrude18" add of existing geometry blind 3.033
delete_face "DeleteFace6"
delete_face "DeleteFace7"
delete_face "DeleteFace8"
offset_faces "OffsetFaces1" distance -0.2
offset_faces "OffsetFaces2" distance 0.2
delete_face "DeleteFace1"
delete_face "DeleteFace2"
delete_face "DeleteFace3"
extrude "Extrude16" cut of existing geometry blind -90
offset_faces "OffsetFaces1" distance -0.1
offset_faces "OffsetFaces2" distance -0.1
sketch "Sketch3" plane through (0, 107, 0) normal (0, -1, 0) x axis (1, 0, 0)
  line L1 (14.1, -14.1) -> (-14.1, -14.1)
  line L2 (14.1, 14.1) -> (14.1, -14.1)
  line L3 (-14.1, 14.1) -> (14.1, 14.1)
  line L4 (-14.1, -14.1) -> (-14.1, 14.1)
  line L5 (-12.1, -12.1) -> (12.1, -12.1)
  line L6 (-12.1, 12.1) -> (-12.1, -12.1)
  line L7 (12.1, 12.1) -> (-12.1, 12.1)
  line L8 (12.1, -12.1) -> (12.1, 12.1)
  line L9 (50, 50) -> (50, -50)
  line L10 (-50, 50) -> (50, 50)
  line L11 (-50, -50) -> (-50, 50)
  line L12 (50, -50) -> (-50, -50)
  line L13 (-12, -12) -> (12, -12)
  line L14 (-12, 12) -> (-12, -12)
  line L15 (12, 12) -> (-12, 12)
  line L16 (12, -12) -> (12, 12)
  circle C1 centre (0, 0) radius 9.5
  circle C2 centre (-3.3, -5.3) radius 1.65
  circle C3 centre (3.3, 5.3) radius 1.65
  circle C4 centre (3.3, 5.3) radius 1.45
  circle C5 centre (-3.3, -5.3) radius 1.45
  dimension "d340" = 0.1
  dimension "d353" = -0.2
  dimension "d354" = -0.2 (= "d353")
extrude "Extrude3" add sketch "Sketch3" profile of C1 L16 L14 L15 L13 C2 C3 C4 C5 along normal blind 3
extrude "Extrude7" add sketch "Sketch3" profile of C4 C5 against normal blind 11
work_axis "WorkAxis1"
work_plane "WorkPlane1" RotateAngle 0
sketch "Sketch7" plane through (0, 0, 5.3) normal (0, 0, 1) x axis (1, 0, 0)
  line L1 (1.85, 118) -> (4.75, 118)
  line L2 (1.65, 115.56) -> (4.95, 115.56)
  line L3 (5.75, 115.86) -> (4.75, 118)
  line L4 (4.75, 118) -> (3.3, 118)
  line L5 (3.3, 118) -> (3.3, 115.56)
  line L6 (3.3, 115.86) -> (5.75, 115.86)
  point P7 (3.3, 115.56)
  point P8 (3.3, 118)
  point P2 (4.75, 118)
  point P9 (4.75, 118)
  point P10 (4.75, 118)
  point P11 (3.3, 115.86)
  point P4 (4.95, 115.56)
  point P6 (5.75, 115.86)
  midpoint L2 P7
  midpoint L1 P8
  coincident P2 P9
  coincident P2 P10
  coincident L5 P11
  horizontal L6
  dimension "d386" distance P4 P6 = 0.3
  dimension "d387" distance P4 P6 = 0.8
revolve "Revolve1" sketch "Sketch7" AlongAngle 180
sketch "Sketch8" plane through (0, 118, 0) normal (0, 1, 0) x axis (-1, 0, 0)
  line L1 (-1.85, 5.3) -> (-4.75, 5.3)
  line L2 (-1.85, 10.5004) -> (-1.85, 5.3)
  line L3 (-4.75, 10.3437) -> (-4.75, 5.3)
  line L4 (-7.251, 10.3437) -> (-4.75, 10.3437)
  line L5 (-7.251, 5.3) -> (-7.251, 10.3437)
  line L6 (-7.251, 5.3) -> (-4.75, 5.3)
  line L7 (0.4379, 5.3) -> (-1.85, 5.3)
  line L8 (0.4379, 10.5004) -> (0.4379, 5.3)
  line L9 (-1.85, 10.5004) -> (0.4379, 10.5004)
  arc A1 centre (-3.3, 5.3) radius 1.45 clockwise from (-4.75, 5.3) to (-1.85, 5.3)
  point P3 (-1.85, 5.3)
  point P5 (-1.85, 5.3)
  point P2 (-4.75, 5.3)
  point P7 (-4.75, 5.3)
  coincident P3 P5
  tangent A1 L2
  coincident P2 P7
  tangent A1 L3
  perpendicular L3 L4
  perpendicular L1 L5
  perpendicular L5 L6
  perpendicular L2 L7
  perpendicular L1 L8
  horizontal L9
extrude "Extrude8" cut sketch "Sketch8" profile of L2 L3 L4 L5 L6 L7 L8 L9 against normal blind 4
sketch "Sketch9" plane through (0, 118, 0) normal (0, 1, 0) x axis (-1, 0, 0)
  line L1 (-1.85, 5.3) -> (-3.3, 5.3)
  line L2 (-4.75, 5.3) -> (-3.3, 5.3)
  line L3 (-1.95, 5.8) -> (-3.3, 5.8)
  line L4 (-4.65, 5.8) -> (-3.3, 5.8)
  line L5 (-4.65, 4.8) -> (-3.3, 4.8)
  line L6 (-1.95, 4.8) -> (-3.3, 4.8)
  line L7 (-1.4501, 5.8) -> (-1.95, 5.8)
  line L8 (-1.4501, 4.8) -> (-1.4501, 5.8)
  line L9 (-1.95, 4.8) -> (-1.4501, 4.8)
  line L10 (-4.9221, 4.8) -> (-4.65, 4.8)
  line L11 (-4.9221, 5.8) -> (-4.9221, 4.8)
  line L12 (-4.65, 5.8) -> (-4.9221, 5.8)
  circle C1 centre (-3.3, 5.3) radius 1.45
  point P2 (-3.3, 5.3)
  point P3 (-3.3, 5.3)
  point P4 (-1.85, 5.3)
  point P5 (-4.75, 5.3)
  coincident P2 P3
  coincident C1 P4
  horizontal L1
  coincident C1 P5
  parallel L1 L2
  parallel L3 L7
  perpendicular L7 L8
  parallel L5 L10
  horizontal L12
  vertical L11
  horizontal L9
  dimension "d360" = -0.5
  dimension "d361" = -0.5
extrude "Extrude9" cut sketch "Sketch9" against normal blind 4.5
fillet "Fillet2" radius 0.3
circular_pattern "C-Pattern1" TotalAngle 360
sketch "Sketch11" plane through (0, 109, 0) normal (0, 1, 0) x axis (-1, 0, 0)
  line L1 (14.1, -14.1) -> (-14.1, -14.1)
  line L2 (14.1, 14.1) -> (14.1, -14.1)
  line L3 (-14.1, 14.1) -> (14.1, 14.1)
  line L4 (-14.1, -14.1) -> (-14.1, 14.1)
  line L5 (0, 14.1) -> (0, 0)
  line L6 (-2, 14.1) -> (-2, 0)
  line L7 (2, 14.1) -> (2, 0)
  circle C1 centre (0, 0) radius 9.5
  point P1 (0, 0)
  point P7 (0, 0)
  point P8 (0, 14.1)
  coincident P1 P7
  midpoint L3 P8
  dimension "d371" = -2
  dimension "d372" = 2
extrude "Extrude10" cut sketch "Sketch11" profile of C1 L3 L5 L6 L7 against normal blind 2
circular_pattern "C-Pattern2" TotalAngle 360
draft "Draft1" Angle1 -45 Angle2 0
fillet "Fillet3" radius 0.5
sketch "Sketch12" plane through (0, 107, 0) normal (0, 1, 0) x axis (-1, 0, 0)
  line L1 (2, 12) -> (2, 9.2871)
  line L2 (-2, 12) -> (2, 12)
  line L3 (-2, 9.2871) -> (-2, 12)
  line L4 (-2, -12) -> (-2, -9.2871)
  line L5 (2, -12) -> (-2, -12)
  line L6 (2, -9.2871) -> (2, -12)
  circle C1 centre (3.3, -5.3) radius 1.75
  arc A1 centre (0, 0) radius 9.5 clockwise from (2, 9.2871) to (2, -9.2871)
  circle C2 centre (-3.3, 5.3) radius 1.75
  circle C3 centre (0, 0) radius 4
  arc A2 centre (0, 0) radius 9.5 clockwise from (-2, -9.2871) to (-2, 9.2871)
  point P1 (0, 0)
  point P9 (0, 0)
  coincident P1 P9
  dimension "d379" diameter C3 = 8
extrude "Extrude11" cut sketch "Sketch12" profile of C3 against normal blind 16
combine "Combine1"
sketch "Sketch2" plane through (0, 0, -50) normal (0, 0, -1) x axis (-1, 0, 0)
  line L1 (46.5, 3.5) -> (-46.5, 3.5)
  line L2 (46.5, 103.5) -> (46.5, 3.5)
  line L3 (-46.5, 103.5) -> (46.5, 103.5)
  line L4 (-46.5, 3.5) -> (-46.5, 103.5)
  line L5 (10, 103.5) -> (-10, 103.5)
  line L6 (10, 93.5) -> (10, 103.5)
  line L7 (-5, 88.5) -> (5, 88.5)
  line L8 (-10, 103.5) -> (-10, 93.5)
  line L9 (0, 0) -> (0, 103.5)
  arc A1 centre (-5, 93.5) radius 5 clockwise from (-5, 88.5) to (-10, 93.5)
  arc A2 centre (5, 93.5) radius 5 clockwise from (10, 93.5) to (5, 88.5)
  point P6 (-10, 103.5)
  point P8 (0, 103.5)
  point P1 (0, 0)
  point P9 (0, 0)
  point P7 (10, 103.5)
  horizontal L5
  vertical L6
  horizontal L7
  vertical L8
  coincident L3 P6
  midpoint L3 P8
  coincident P1 P9
  tangent L7 A1
  tangent L8 A1
  tangent L7 A2
  tangent L6 A2
  equal A1 A2
  dimension "d398" distance L6 L8 = 20
  dimension "d399" distance L8 L9 = 10 (= "d398 / 2")
  dimension "d400" distance P7 L7 = 15
  dimension "d401" radius A1 = 5
extrude "Extrude9" cut sketch "Sketch2" profile of L3 L5 L6 L7 L8 A1 A2 against normal blind 10
move "Move1" RotateAngle -180
move "Move2"
move "Move3"
move "Move4"
move "Move5"
move "Move6"
sketch "Sketch13" plane through (0, 104.9, 0) normal (0, 1, 0) x axis (-1, 0, 0)
  dimension "d443" = 3
  dimension "d445" = 3
  dimension "d447" = 3
  dimension "d449" = 3
  dimension "d450" = 0 (= "Text4-Text")
extrude "Extrude20" new body sketch "Sketch13" along normal blind 0.1
move "Move1"
move "Move2"
move "Move3"
move "Move4"
move "Move5"
move "Move6"
move "Move7"
move "Move8"
move "Move9"
move "Move10"
move "Move11"
move "Move12"
move "Move13"
move "Move14"
move "Move15"
move "Move16"
move "Move17"
move "Move18"
move "Move19"
move "Move20"
move "Move21"
sketch "Sketch7" plane through (0, 0, 0) normal (0, 1, 0) x axis (1, 0, 0)
  dimension "d433" = 4
  dimension "d435" = 4
  dimension "d437" = 4
  dimension "d439" = 4
extrude "Extrude2" new body sketch "Sketch7" along normal blind 0.1
move "Move22"
move "Move23"
move "Move8"
move "Move9"
sketch "Sketch3" plane through (0, 2, 0) normal (0, 1, 0) x axis (-1, 0, 0)
  dimension "d405" = 10
  dimension "d406" = 0 (= "Text1-Text")
  dimension "d409" = 10
  dimension "d410" = 0 (= "Text2-Text")
extrude "Extrude10" add sketch "Sketch3" along normal blind 0.1
extrude "Extrude11" add sketch "Sketch3" along normal blind 0.1
rectangular_pattern "R-Pattern1" uSpaceDistance -2.5 vSpaceDistance 0
move "Move10"
move "Move11"
rectangular_pattern "R-Pattern2" uSpaceDistance -2.5 vSpaceDistance 0
move "Move12"
move "Move13"
move "Move14"
move "Move15"
move "Move1"
move "Move2"
move "Move3"
sketch "Sketch4" plane through (0, -10.5, 0) normal (0, 1, 0) x axis (-1, 0, 0)
  line L1 (-119, 75) -> (-119, 65)
  line L2 (-104, 80) -> (-114, 80)
  line L3 (-99, 65) -> (-99, 75)
  line L4 (-62.5, 65) -> (-99, 65)
  line L5 (-62.5, 165) -> (-62.5, 65)
  line L6 (-155.5, 165) -> (-62.5, 165)
  line L7 (-155.5, 65) -> (-155.5, 165)
  line L8 (-119, 65) -> (-155.5, 65)
  line L9 (-155.5, 65) -> (-62.5, 165)
  curve K1
  curve K2
  curve K3
  curve K4
  arc A1 centre (-114, 75) radius 5 clockwise from (-119, 75) to (-114, 80)
  arc A2 centre (-104, 75) radius 5 clockwise from (-104, 80) to (-99, 75)
  point P11 (-62.5, 165)
  point P14 (-62.5, 165)
  point P13 (-155.5, 65)
  point P15 (-155.5, 65)
  coincident P11 P14
  coincident P13 P15
  horizontal K3
  midpoint L9
  dimension "d421" Text1-Height = 10
  dimension "d422" Text = 0 (= "Text1-Text")
extrude "Extrude12" add sketch "Sketch4" along normal blind 0.1
sketch "Sketch5" plane through (0, -10.5, 0) normal (0, 1, 0) x axis (-1, 0, 0)
  line L1 (-122.1, -12.1) -> (-97.9, -12.1)
  line L2 (-122.1, 12.1) -> (-122.1, -12.1)
  line L3 (-97.9, 12.1) -> (-122.1, 12.1)
  line L4 (-97.9, -12.1) -> (-97.9, 12.1)
  line L5 (-160, -50) -> (-160, 50)
  line L6 (-60, -50) -> (-160, -50)
  line L7 (-60, 50) -> (-60, -50)
  line L8 (-160, 50) -> (-60, 50)
  curve K1
  curve K2
  curve K3
  curve K4
  dimension "d425" Text1-Height = 8
  dimension "d426" Text = 0 (= "Text1-Text")
extrude "Extrude13" add sketch "Sketch5" along normal blind 0.1
sketch "Sketch6" plane through (0, -12.5, 0) normal (0, -1, 0) x axis (1, 0, 0)
  dimension "d429" = 10
extrude "Extrude1" new body sketch "Sketch6" blind 0.1
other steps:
base_feature "Base Feature" bodies "Lampshade"
create_component "CreateComponent1"
create_component "CreateComponent3"
create_component "CreateComponent4"
create_component "CreateComponent2"
remove_body "RemoveBody3"
create_component "CreateComponent5"
create_component "CreateComponent6"
named bodies: "Lamp Holder", "Lampshade"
